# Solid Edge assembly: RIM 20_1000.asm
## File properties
Title: Zylinder
Author: ahadarics
Template: iso metric assembly.asm
Last saved by: ahadarics
Revision: 31
Application: Solid Edge
Username: ahadarics
Dokumentum tartalom típus: 1
Document Number: RIM 20/1000
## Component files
Kit_2.par
Profilrohr.par
Kolbenstange.par
Kit_1.par
Mutter_1.par
Mutter_2.par
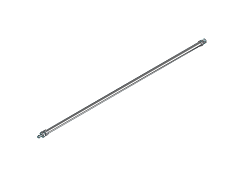
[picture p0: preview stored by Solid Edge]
